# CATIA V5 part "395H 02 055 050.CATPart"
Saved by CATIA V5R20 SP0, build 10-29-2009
Part number: Part1
Source: Unknown
Bounding box of the stored display mesh (mm): x -30 to 30, y -30 to 30, z -26 to 26
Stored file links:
  C:\Users\Utente\Desktop\3D files 395H FORD\395H 02 055 050.CATPart
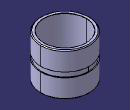
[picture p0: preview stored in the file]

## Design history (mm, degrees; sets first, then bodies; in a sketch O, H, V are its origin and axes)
Body1 (main body)
  Solid1 "PartBody": solid without history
